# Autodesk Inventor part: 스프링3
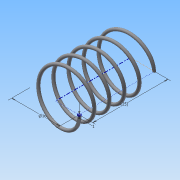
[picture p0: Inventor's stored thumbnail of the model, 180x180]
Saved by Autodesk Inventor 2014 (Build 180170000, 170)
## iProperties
Created: 2015-06
Part Number: 스프링3
Material: 강철, 연강
Document SubType Name: Modeling
Designer: Administrator
Density: 7.86 g/cm^3
Appearance: 강철
Mass: 1.5292 g
Surface Area: 7.8715 cm^2
Volume: 0.194555 cm^3
Author: Administrator
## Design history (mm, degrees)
sketch "스케치1"
  geometry: L1 (0, 0)-(8, 0); L2 (8, 0)-(8, 14.5); L3 (8, 14.5)-(0, 14.5); L4 (0, 14.5)-(0, 0); C1 r 0.5 at (8, 0)
  constraints: 8 end point, 2 parallel, 1 centre point, 1 coincident, 1 horizontal, 1 perpendicular
  dimensions: "d0" = 16 diameter of L2 L4; "d1" = 14.5 distance of L1.end L2.end (derived); "d2" = 1 diameter of C1
feature "코일1" sketch "스케치1" pitch "d3" = 10; turns "d5" = 5; dims "d4" = 14.5 (= d1), "d6" = 0, angle "d7" = 90 deg, angle "d8" = 90 deg, "d9" = 0, "d10" = 0
sketch "스케치2"
  geometry: L1 (-8.5, 0)-(-7.5, 0) reference; 1 further point
  constraints: 1 horizontal alignment
extrude "돌출1" cut sketch "스케치2" stored distance "d11" = 10; taper "d12" = 0 deg
node "작업 평면1"
sketch "스케치3"
  geometry: L1 (8.5, 0)-(7.5, 0) reference; 1 further point
  constraints: 1 horizontal alignment
extrude "돌출2" cut sketch "스케치3" stored distance "d14" = 10; taper "d15" = 0 deg
node "솔리드1"
node "절단 모서리 투영1"
node "절단 모서리 투영2"
other parameters: "d13" = -14.5 (= -d1)
